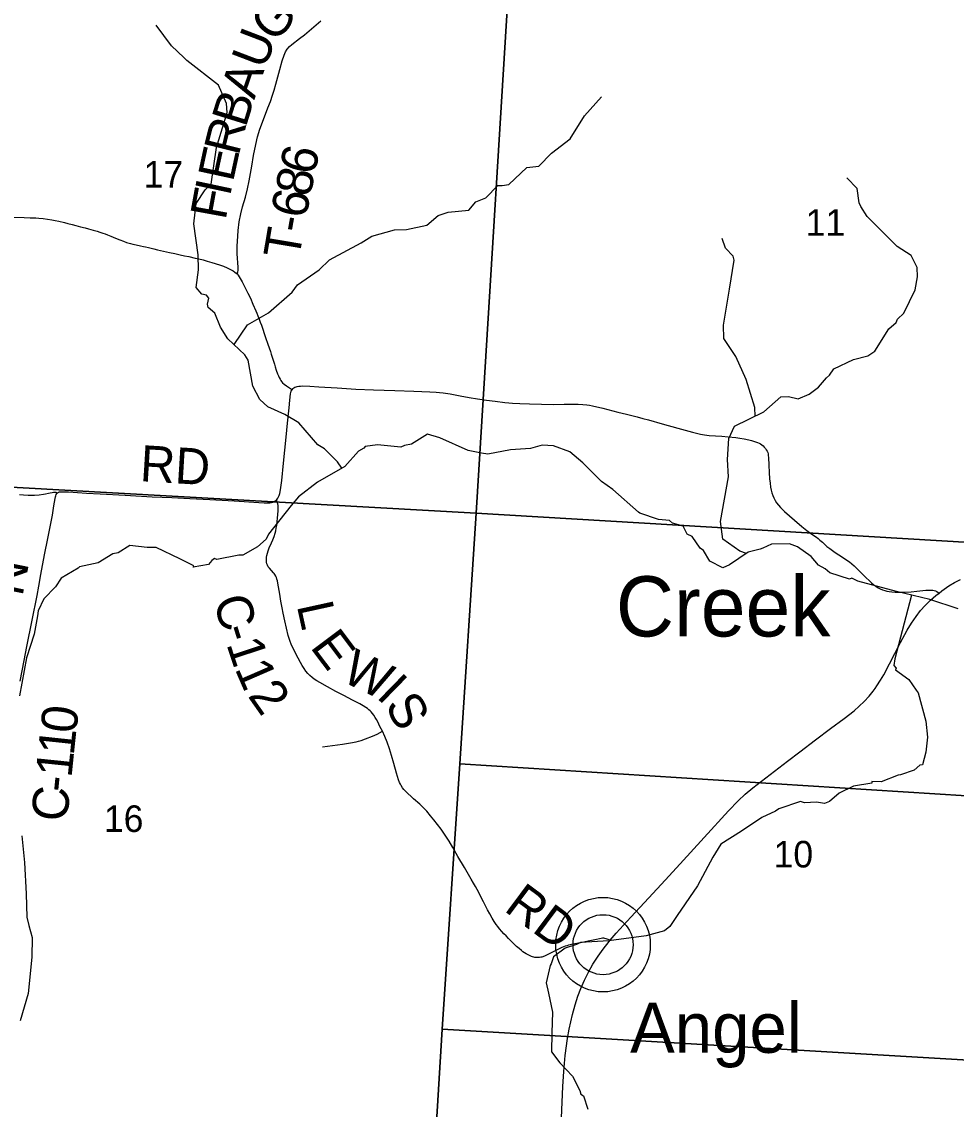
# Model space of a CAD drawing. Extents: x 396.2 to 468.4, y 232.6 to 279.1.
# Drawn here: x 418.928 to 420.398, y 273.414 to 275.126 of the extents above; entities that cross this region are included whole.
import ezdxf

# ---------------------------------------------------------------- set-up
doc = ezdxf.new("R2010")
doc.units = 0
for name, color, linetype in [('GM_X_County_Road', 7, 'Continuous'), ('GM_X_County_Road_Text', 7, 'Continuous'), ('GM_X_Minor_River', 7, 'Continuous'), ('GM_X_Minor_River_Text', 7, 'Continuous'), ('GM_X_Section', 7, 'Continuous'), ('GM_X_Section_Text', 7, 'Continuous'), ('GM_X_State_Route', 7, 'Continuous'), ('GM_X_Township_Road', 7, 'Continuous'), ('GM_X_Township_Road_Text', 7, 'Continuous'), ('GM_X_Unincorporated', 7, 'Continuous'), ('GM_X_Unincorporated_Location', 7, 'Continuous'), ('GM_X_Unincorporated_Text', 7, 'Continuous')]:
    doc.layers.add(name, color=color, linetype=linetype)

msp = doc.modelspace()

# ---------------------------------------------------------------- linework, layer by layer
at = {"layer": 'GM_X_County_Road'}
for points in [[(418.9108, 274.8182), (418.9315, 274.8177), (418.9414, 274.8174), (418.9501, 274.817), (418.9548, 274.8167), (418.9618, 274.8162), (418.9686, 274.8152), (418.9752, 274.8142), (418.9804, 274.8132), (418.9861, 274.8121), (418.9953, 274.8099), (419.0006, 274.8086), (419.0074, 274.8068), (419.0131, 274.8052), (419.0205, 274.8032), (419.0275, 274.8013), (419.033, 274.7998), (419.0404, 274.7977), (419.0464, 274.7961), (419.0506, 274.7949), (419.0553, 274.7933), (419.0593, 274.7919), (419.0628, 274.7905), (419.068, 274.7884), (419.0754, 274.7852), (419.0822, 274.7824), (419.0879, 274.7803), (419.0927, 274.7786), (419.0989, 274.7769), (419.1029, 274.7758), (419.108, 274.7747), (419.1147, 274.7732), (419.1197, 274.7721), (419.1227, 274.7714), (419.1274, 274.7704), (419.1315, 274.7694), (419.1358, 274.7685), (419.1417, 274.7671), (419.1603, 274.7628), (419.1688, 274.761), (419.1772, 274.7591), (419.1841, 274.7576), (419.1906, 274.7562), (419.2006, 274.7539), (419.2067, 274.7525), (419.2133, 274.7509), (419.2198, 274.7491), (419.2269, 274.7472), (419.2392, 274.7432), (419.2453, 274.741), (419.2509, 274.7388), (419.2543, 274.7372), (419.2575, 274.7356), (419.2606, 274.7338), (419.2631, 274.732), (419.2654, 274.7302), (419.2667, 274.7289), (419.2685, 274.7268), (419.2702, 274.7245), (419.2717, 274.722), (419.2747, 274.7166), (419.2802, 274.7059), (419.2837, 274.6987), (419.2877, 274.6906), (419.2917, 274.6812), (419.2963, 274.6708), (419.2978, 274.6671), (419.2994, 274.6631), (419.301, 274.6591), (419.3031, 274.6533), (419.3051, 274.6481), (419.3116, 274.6289), (419.3153, 274.6184), (419.3192, 274.607), (419.3205, 274.6029), (419.3226, 274.5964), (419.3254, 274.5869), (419.3267, 274.5828), (419.3284, 274.5777), (419.3305, 274.5716), (419.3317, 274.5686), (419.3328, 274.566), (419.3343, 274.5633), (419.3355, 274.5613), (419.3368, 274.5596), (419.3382, 274.5578), (419.3407, 274.5556), (419.3443, 274.5529), (419.3521, 274.5476), (419.3533, 274.5467)], [(418.9841, 274.3842), (418.9857, 274.3853), (418.9873, 274.3858), (418.9892, 274.3861), (418.9915, 274.3862), (419.0017, 274.3858), (419.03, 274.3841), (419.0511, 274.3828), (419.0908, 274.3807), (419.133, 274.3783), (419.164, 274.3769), (419.1925, 274.3755), (419.2236, 274.3739), (419.262, 274.3716), (419.3011, 274.3693), (419.3091, 274.3688), (419.3159, 274.3686), (419.3184, 274.3688), (419.3207, 274.3691), (419.3229, 274.3697), (419.3249, 274.3707), (419.3266, 274.3717), (419.3285, 274.3731), (419.3297, 274.3743), (419.3308, 274.3758), (419.3321, 274.378), (419.3331, 274.3804), (419.334, 274.3835), (419.335, 274.3891), (419.3369, 274.4038), (419.3397, 274.4311), (419.3439, 274.4718), (419.3462, 274.4942), (419.3487, 274.5183), (419.3497, 274.5305), (419.3509, 274.5401), (419.3514, 274.5423), (419.3519, 274.5442), (419.3527, 274.5458), (419.3533, 274.5467)], [(419.3533, 274.5467), (419.3548, 274.5486), (419.3562, 274.5497), (419.3578, 274.5507), (419.3596, 274.5515), (419.3615, 274.552), (419.3637, 274.5523), (419.3664, 274.5525), (419.37, 274.5526), (419.3813, 274.5522), (419.3951, 274.5513), (419.4241, 274.5496), (419.4534, 274.5478), (419.4815, 274.5466), (419.5148, 274.5453), (419.5446, 274.5443), (419.5701, 274.5434), (419.5799, 274.5428), (419.5854, 274.5424), (419.5909, 274.5419), (419.602, 274.5402), (419.6179, 274.5373), (419.6319, 274.5345), (419.6448, 274.5322), (419.6591, 274.5303), (419.6728, 274.5286), (419.6878, 274.5268), (419.6943, 274.5263), (419.7003, 274.5258), (419.7115, 274.5252), (419.727, 274.5246), (419.7457, 274.524), (419.7643, 274.5237), (419.7811, 274.524), (419.7932, 274.5241), (419.8035, 274.5239), (419.8107, 274.5236), (419.817, 274.5231), (419.8211, 274.5225), (419.826, 274.5216), (419.8424, 274.5176), (419.8658, 274.5114), (419.8795, 274.508), (419.8961, 274.5039), (419.9051, 274.5016), (419.914, 274.4992), (419.9354, 274.4932), (419.9604, 274.4862), (419.9834, 274.4798), (419.9893, 274.4782), (419.996, 274.4767), (420.0022, 274.4757), (420.0096, 274.4749), (420.0294, 274.4736), (420.0393, 274.4726), (420.0515, 274.4713), (420.0577, 274.4705), (420.0648, 274.4693), (420.0717, 274.468), (420.0761, 274.4669), (420.0794, 274.4659), (420.0824, 274.4649), (420.0854, 274.4637), (420.0879, 274.4626), (420.0902, 274.4614), (420.0923, 274.46), (420.0943, 274.4584), (420.0962, 274.4565), (420.0979, 274.4544), (420.0993, 274.4522), (420.1007, 274.45), (420.1016, 274.4478), (420.1021, 274.4457), (420.1024, 274.4434), (420.1026, 274.4402), (420.1031, 274.4282), (420.1038, 274.4167), (420.1045, 274.4064), (420.1053, 274.3995), (420.1062, 274.3934), (420.107, 274.3885), (420.108, 274.3843), (420.1095, 274.3801), (420.111, 274.3764), (420.1133, 274.3723), (420.1156, 274.3686), (420.1185, 274.3649), (420.1216, 274.3615), (420.1279, 274.3551), (420.1439, 274.3413), (420.1552, 274.3316), (420.1632, 274.3251), (420.1708, 274.3195), (420.1783, 274.3145), (420.1811, 274.3125), (420.1838, 274.31), (420.1876, 274.3068), (420.1913, 274.3033), (420.1948, 274.3), (420.1992, 274.2966), (420.2078, 274.2906), (420.2193, 274.2831), (420.2244, 274.2796), (420.2301, 274.2757), (420.2338, 274.2729), (420.2377, 274.2696), (420.242, 274.2656), (420.2527, 274.2545), (420.2648, 274.2427), (420.2684, 274.2397), (420.2717, 274.2373), (420.2752, 274.2351), (420.2786, 274.2335), (420.2822, 274.232), (420.2856, 274.2308), (420.289, 274.2299), (420.2926, 274.2291), (420.2967, 274.2287), (420.3022, 274.2283), (420.308, 274.2282), (420.3176, 274.2283), (420.3271, 274.2287), (420.3361, 274.2296), (420.3457, 274.2306), (420.3506, 274.231), (420.3556, 274.2312), (420.3591, 274.2312), (420.3612, 274.2311), (420.3634, 274.2308), (420.3657, 274.23), (420.3675, 274.229), (420.3713, 274.2268)], [(418.9255, 274.0883), (418.9315, 274.1206), (418.9359, 274.1425), (418.9441, 274.184), (418.952, 274.2229), (418.9549, 274.2376), (418.9581, 274.2559), (418.9607, 274.27), (418.9643, 274.2895), (418.9684, 274.3102), (418.9726, 274.3309), (418.9761, 274.3493), (418.9785, 274.364), (418.9804, 274.3757), (418.9809, 274.3779), (418.9815, 274.3799), (418.9823, 274.3819), (418.9831, 274.3832), (418.9841, 274.3842)], [(419.8536, 273.6802), (419.8492, 273.6818), (419.8472, 273.6825), (419.8455, 273.683), (419.8435, 273.6834), (419.8416, 273.6833), (419.8396, 273.6831), (419.8297, 273.6811), (419.8189, 273.6788), (419.8097, 273.6769), (419.7954, 273.6741), (419.7884, 273.6724), (419.7856, 273.6717), (419.7829, 273.6708), (419.7778, 273.6688), (419.7725, 273.6665), (419.7631, 273.6616), (419.7587, 273.6593), (419.7537, 273.6569), (419.7504, 273.6554), (419.7464, 273.6539), (419.7444, 273.6534), (419.7424, 273.653), (419.7405, 273.6529), (419.7387, 273.6529), (419.737, 273.6529), (419.7352, 273.6532), (419.7337, 273.6535), (419.7317, 273.654), (419.7299, 273.6547), (419.7278, 273.6555), (419.7245, 273.6572), (419.7215, 273.6588), (419.7189, 273.6605), (419.7165, 273.6622), (419.7141, 273.6642), (419.7103, 273.6673), (419.7066, 273.6705), (419.699, 273.6778), (419.6938, 273.6831), (419.6899, 273.687), (419.6866, 273.6904), (419.6835, 273.6939), (419.6796, 273.6985), (419.677, 273.7017), (419.6743, 273.7053), (419.6714, 273.7098), (419.6681, 273.7152), (419.6643, 273.7218), (419.6608, 273.7284), (419.6576, 273.7346), (419.6543, 273.7408), (419.6509, 273.7476), (419.648, 273.7534), (419.6445, 273.76), (419.6417, 273.7649), (419.6386, 273.7703), (419.635, 273.7764), (419.6243, 273.7946), (419.6142, 273.8121), (419.6063, 273.8261), (419.6002, 273.8363), (419.5942, 273.8457), (419.5877, 273.8549), (419.582, 273.8626), (419.5763, 273.8698), (419.571, 273.8763), (419.5651, 273.8832), (419.5622, 273.8865), (419.5594, 273.8894), (419.5569, 273.8918), (419.5544, 273.8943), (419.5444, 273.9031), (419.5319, 273.9147), (419.5293, 273.9176), (419.5271, 273.9204), (419.525, 273.9236), (419.5237, 273.9259), (419.5224, 273.9286), (419.5208, 273.9326), (419.5173, 273.943), (419.5131, 273.9587), (419.5099, 273.971), (419.5066, 273.9815), (419.503, 273.9918), (419.4993, 274.0011), (419.4954, 274.0091), (419.4915, 274.0168), (419.488, 274.0239), (419.486, 274.0277), (419.4842, 274.031), (419.482, 274.0345), (419.4799, 274.0372), (419.4778, 274.0396), (419.4759, 274.0414), (419.474, 274.0431), (419.4719, 274.0449), (419.4694, 274.0467), (419.4652, 274.0492), (419.4598, 274.0522), (419.4482, 274.0582), (419.4346, 274.0653), (419.4219, 274.0717), (419.4088, 274.079), (419.3968, 274.0857), (419.3921, 274.0887), (419.3881, 274.0914), (419.3847, 274.0939), (419.3814, 274.0967), (419.378, 274.1001), (419.3749, 274.104), (419.3721, 274.1079), (419.3691, 274.1125), (419.3666, 274.1173), (419.3629, 274.124), (419.3599, 274.1299), (419.3568, 274.1359), (419.354, 274.1416), (419.3519, 274.1463), (419.3502, 274.1507), (419.3488, 274.1551), (419.3473, 274.16), (419.3443, 274.1717), (419.3418, 274.183), (419.3391, 274.1951), (419.3374, 274.2036), (419.3357, 274.2139), (419.3339, 274.2251), (419.331, 274.2423), (419.3301, 274.2461), (419.3293, 274.2488), (419.3285, 274.2512), (419.3277, 274.2531), (419.3263, 274.2558), (419.3253, 274.2573), (419.3241, 274.2588), (419.3175, 274.266), (419.3158, 274.2681), (419.3146, 274.2704), (419.3135, 274.2728), (419.313, 274.2755), (419.3128, 274.2776), (419.3129, 274.2801), (419.3132, 274.283), (419.3137, 274.2859), (419.3145, 274.2894), (419.3158, 274.2934), (419.3173, 274.2977), (419.3209, 274.306), (419.323, 274.3107), (419.3249, 274.3157), (419.3266, 274.3211), (419.3275, 274.3247), (419.3284, 274.3291), (419.3292, 274.3333), (419.3299, 274.3393), (419.3305, 274.3448), (419.3314, 274.3562), (419.3314, 274.3594), (419.3314, 274.3618), (419.3312, 274.3644), (419.3306, 274.3671), (419.3298, 274.3695), (419.3285, 274.3731)]]:
    msp.add_lwpolyline(points, dxfattribs=at)
at = {"layer": 'GM_X_Minor_River'}
for points in [[(419.4314, 274.4232), (419.4245, 274.4332), (419.404, 274.4536), (419.3936, 274.46), (419.364, 274.4944), (419.3421, 274.5076), (419.3149, 274.5198), (419.3024, 274.5313), (419.2917, 274.5525), (419.2842, 274.5934), (419.2788, 274.6019), (419.2524, 274.627), (419.2404, 274.6453), (419.2317, 274.6672), (419.2213, 274.6759), (419.2204, 274.6812), (419.2225, 274.691), (419.2185, 274.6957), (419.211, 274.6971), (419.2026, 274.7076), (419.2061, 274.7356), (419.2053, 274.7588), (419.1985, 274.808), (419.2021, 274.8398), (419.2167, 274.8613), (419.2261, 274.8705), (419.2343, 274.928), (419.2511, 274.9833), (419.2503, 274.9973), (419.2376, 275.0259), (419.1874, 275.065), (419.183, 275.0697), (419.1635, 275.0882), (419.1392, 275.1205)], [(419.2619, 274.6179), (419.2833, 274.6488), (419.3163, 274.6675), (419.3536, 274.7005), (419.3619, 274.7116), (419.3959, 274.7352), (419.4122, 274.751), (419.4622, 274.7779), (419.4788, 274.7884), (419.5142, 274.7983), (419.5335, 274.7988), (419.5651, 274.8058), (419.5833, 274.8211), (419.599, 274.8263), (419.6316, 274.8291), (419.6426, 274.8424), (419.6582, 274.8487), (419.677, 274.8679), (419.6838, 274.8681), (419.6944, 274.8696), (419.7224, 274.8964), (419.7414, 274.8985), (419.7613, 274.9191), (419.7907, 274.9417), (419.8134, 274.9778), (419.8403, 275.0077)], [(420.0684, 274.289), (420.0579, 274.2926), (420.0309, 274.3117), (420.0272, 274.3391), (420.0399, 274.4097), (420.0385, 274.4367), (420.0403, 274.4701), (420.0495, 274.4892), (420.0956, 274.512), (420.1224, 274.5354), (420.1345, 274.5362), (420.1495, 274.5323), (420.1667, 274.5397), (420.1814, 274.5506), (420.1943, 274.5654), (420.1986, 274.5698), (420.2057, 274.5795), (420.2368, 274.5941), (420.2589, 274.6002), (420.2701, 274.6074), (420.2919, 274.6428), (420.3039, 274.6523), (420.3056, 274.6576), (420.3157, 274.6671), (420.3335, 274.7041), (420.3375, 274.7245), (420.3368, 274.739), (420.3272, 274.7579), (420.3053, 274.7723), (420.258, 274.8193), (420.2479, 274.8352), (420.2454, 274.841), (420.2423, 274.8635), (420.2262, 274.88)], [(420.082, 274.5053), (420.0814, 274.5189), (420.0676, 274.563), (420.0514, 274.5992), (420.0326, 274.6276), (420.032, 274.6481), (420.0417, 274.7051), (420.0488, 274.7505), (420.0471, 274.757), (420.035, 274.7695), (420.0298, 274.7849)], [(420.4011, 274.202), (420.3568, 274.2164), (420.3043, 274.2292), (420.2434, 274.2454), (420.2339, 274.2503), (420.2305, 274.2488), (420.1995, 274.2586), (420.192, 274.2646), (420.1814, 274.2707), (420.17, 274.2843), (420.1485, 274.2995), (420.136, 274.304), (420.1076, 274.3036), (420.0937, 274.2971), (420.0899, 274.2959), (420.071, 274.2913), (420.0415, 274.2711), (420.0309, 274.2662), (420.0105, 274.2768), (420.0007, 274.2938), (419.9954, 274.2972), (419.9825, 274.3158), (419.9749, 274.3192), (419.9685, 274.3318), (419.9519, 274.3367), (419.9473, 274.3408), (419.9295, 274.3427), (419.9004, 274.3525), (419.8982, 274.354), (419.8581, 274.3897), (419.8403, 274.4022), (419.8108, 274.4317), (419.79, 274.4492), (419.7646, 274.4582), (419.7468, 274.4593), (419.7283, 274.4544), (419.697, 274.452), (419.6611, 274.4455), (419.6512, 274.447), (419.6304, 274.4511), (419.5858, 274.4711), (419.5661, 274.4768), (419.5412, 274.4611), (419.5302, 274.4592), (419.5246, 274.4565), (419.4879, 274.4599), (419.4682, 274.4576), (419.466, 274.4549), (419.458, 274.4499), (419.4362, 274.4257)], [(419.4362, 274.4257), (419.3931, 274.4011), (419.3636, 274.3779), (419.3519, 274.3645), (419.316, 274.3196), (419.3123, 274.3116), (419.299, 274.2994), (419.2756, 274.2861), (419.2696, 274.2864), (419.2348, 274.2795), (419.231, 274.281), (419.2269, 274.278), (419.2219, 274.2719), (419.1978, 274.2676), (419.1985, 274.2695), (419.1766, 274.2805), (419.1395, 274.2983), (419.1251, 274.2986)], [(419.1251, 274.2986), (419.0979, 274.3016), (419.0798, 274.2898), (419.0711, 274.2883), (419.0481, 274.2741), (419.0186, 274.268), (419.0167, 274.2661), (418.9899, 274.25), (418.9808, 274.2367), (418.9627, 274.2177), (418.9536, 274.1987), (418.9529, 274.1907), (418.9472, 274.1618), (418.9352, 274.1245), (418.9246, 274.0648)], [(420.3277, 274.2234), (420.3018, 274.1234)], [(420.3018, 274.1234), (420.3002, 274.1128), (420.3036, 274.1083), (420.3029, 274.106), (420.3237, 274.0908), (420.335, 274.0738), (420.3384, 274.0696), (420.3502, 274.0252), (420.3529, 273.9997), (420.3506, 273.9765), (420.345, 273.9563), (420.3408, 273.956), (420.3321, 273.9479), (420.3106, 273.9407), (420.3068, 273.9399), (420.28, 273.9296), (420.2656, 273.9299), (420.2652, 273.9273), (420.2365, 273.923), (420.2138, 273.9116), (420.1987, 273.8986), (420.1908, 273.8955), (420.1783, 273.8974), (420.1594, 273.8966), (420.1534, 273.8989), (420.119, 273.887), (420.1141, 273.8836), (420.0922, 273.8737), (420.0604, 273.8519), (420.0279, 273.8313), (420.0151, 273.8108), (419.9913, 273.7659), (419.9592, 273.719), (419.9475, 273.7019), (419.9392, 273.695), (419.9105, 273.6874), (419.8515, 273.6792), (419.8069, 273.6765), (419.8005, 273.6738), (419.7831, 273.6677), (419.7646, 273.654), (419.7608, 273.6433), (419.7593, 273.6403), (419.7529, 273.6133), (419.7567, 273.5969), (419.7632, 273.5669), (419.7617, 273.5346), (419.7614, 273.5046), (419.7746, 273.4871), (419.7947, 273.4666), (419.806, 273.4439), (419.8075, 273.4378), (419.8117, 273.4355), (419.8185, 273.4142)], [(418.9279, 273.8447), (418.9321, 273.8025), (418.9351, 273.7531), (418.9359, 273.7166), (418.9393, 273.7037), (418.9443, 273.6844), (418.9439, 273.6539), (418.9379, 273.5965), (418.9255, 273.5535)]]:
    msp.add_lwpolyline(points, dxfattribs=at)
at = {"layer": 'GM_X_Section'}
for points in [[(418.6585, 275.4056), (419.7043, 275.3495), (419.6431, 274.3525), (418.6011, 274.4105)], [(419.7043, 275.3495), (420.7452, 275.2968), (420.6845, 274.2907), (419.6431, 274.3525)], [(418.6011, 274.4105), (419.6431, 274.3525), (419.617, 273.9581), (419.5894, 273.5404), (419.5789, 273.368), (418.9789, 273.3919), (418.5411, 273.4101), (418.5524, 273.5824), (418.5769, 274)], [(419.6431, 274.3525), (420.6845, 274.2907), (420.6634, 273.8917), (419.617, 273.9581)], [(420.6634, 273.8917), (420.6398, 273.4786), (419.5894, 273.5404), (419.617, 273.9581)], [(419.5894, 273.5404), (420.6398, 273.4786), (420.6297, 273.3021), (419.5789, 273.368)]]:
    msp.add_lwpolyline(points, close=True, dxfattribs=at)
at = {"layer": 'GM_X_State_Route'}
for points in [[(419.8536, 273.6802), (419.8631, 273.6912), (419.8861, 273.7166), (419.9146, 273.7472), (419.9401, 273.7746), (419.9639, 273.8008), (420.0016, 273.8421), (420.0398, 273.8838), (420.0553, 273.8999), (420.0661, 273.91), (420.078, 273.9199), (420.1326, 273.9621), (420.1519, 273.9766), (420.1767, 273.9955), (420.2005, 274.0134), (420.2219, 274.0294), (420.2375, 274.0414), (420.2457, 274.0485), (420.2536, 274.0562), (420.2614, 274.0645), (420.2676, 274.0722), (420.2706, 274.0765), (420.2734, 274.0807), (420.279, 274.0894), (420.2841, 274.0981), (420.3107, 274.1491), (420.3212, 274.1682), (420.3277, 274.1792), (420.335, 274.1899), (420.3421, 274.1991), (420.3492, 274.2071), (420.3576, 274.2154), (420.3663, 274.2228), (420.3713, 274.2268), (420.3754, 274.23), (420.3867, 274.2379), (420.3957, 274.2433), (420.4051, 274.248)], [(419.7756, 273.3634), (419.7793, 273.4503), (419.7807, 273.4739), (419.7828, 273.4989), (419.7867, 273.5259), (419.7894, 273.5405), (419.7944, 273.5634), (419.7985, 273.5788), (419.8029, 273.5924), (419.8075, 273.6042), (419.8133, 273.6173), (419.8197, 273.63), (419.8267, 273.6425), (419.8347, 273.655), (419.8425, 273.6662), (419.852, 273.6784), (419.8536, 273.6802)]]:
    msp.add_lwpolyline(points, dxfattribs=at)
at = {"layer": 'GM_X_Township_Road'}
for points in [[(419.2667, 274.7289), (419.2678, 274.7323), (419.2683, 274.7345), (419.2685, 274.7367), (419.2684, 274.7395), (419.2669, 274.7608), (419.2666, 274.7668), (419.2667, 274.7728), (419.2677, 274.7882), (419.2685, 274.7974), (419.2702, 274.8109), (419.2726, 274.8237), (419.2751, 274.8345), (419.2797, 274.85), (419.283, 274.8627), (419.2856, 274.8755), (419.2898, 274.8987), (419.2927, 274.9153), (419.2962, 274.9329), (419.2991, 274.9449), (419.3026, 274.9568), (419.3065, 274.9679), (419.3153, 274.9903), (419.3191, 275.0001), (419.3225, 275.0101), (419.3251, 275.0184), (419.3277, 275.0274), (419.331, 275.0394), (419.3342, 275.0507), (419.3378, 275.0645), (419.3407, 275.0734), (419.3429, 275.0784), (419.3455, 275.0825), (419.349, 275.0868), (419.3526, 275.0901), (419.3651, 275.0993), (419.3729, 275.1054), (419.3877, 275.1178), (419.3983, 275.1274)], [(418.9245, 274.382), (418.9305, 274.3814), (418.9379, 274.3809), (418.9478, 274.3808), (418.9552, 274.3814), (418.9619, 274.3824), (418.9655, 274.3831), (418.9698, 274.384), (418.9728, 274.3847), (418.9758, 274.3852), (418.9778, 274.3855), (418.9793, 274.3856), (418.9803, 274.3855), (418.9814, 274.3853), (418.9827, 274.3848), (418.9841, 274.3842)], [(419.401, 273.9845), (419.4166, 273.9868), (419.4324, 273.989), (419.4453, 273.9909), (419.4539, 273.9927), (419.4578, 273.9936), (419.4617, 273.9947), (419.4688, 273.9971), (419.4798, 274.0015), (419.4872, 274.0048), (419.4954, 274.0091)]]:
    msp.add_lwpolyline(points, dxfattribs=at)
at = {"layer": 'GM_X_Unincorporated'}
for radius in [0.0744, 0.0472]:
    msp.add_circle((419.8425, 273.6733), radius, dxfattribs=at)
at = {"layer": 'GM_X_Unincorporated_Location'}
msp.add_line((419.8425, 273.6733), (419.8425, 273.6733), dxfattribs=at)

# ---------------------------------------------------------------- texts
at = {"layer": 'GM_X_County_Road_Text'}
for s, height, rotation, p in [('RD', 0.05682, 356.5467, (419.113, 274.4029)), ('N', 0.0568, 78.5982, (418.9288, 274.2202)), ('C', 0.0568, 286.8772, (419.2287, 274.215)), ('L', 0.0568, 282.361, (419.3605, 274.2072)), ('-', 0.0568, 287.1602, (419.2423, 274.1701)), ('E', 0.0568, 306.9638, (419.3806, 274.1417)), ('1', 0.0568, 288.1955, (419.2496, 274.1467)), ('W', 0.0568, 334.3897, (419.4289, 274.0891)), ('1', 0.0568, 293.4754, (419.2625, 274.1081)), ('I', 0.0568, 315.7314, (419.4843, 274.0634)), ('2', 0.0568, 305.1273, (419.2826, 274.065)), ('S', 0.0568, 298.4736, (419.4983, 274.0507)), ('0', 0.0568, 83.261, (419.0133, 274.0044)), ('1', 0.0568, 83.9313, (419.0096, 273.9698)), ('1', 0.0568, 84.1509, (419.0061, 273.935)), ('C', 0.0568, 84.2255, (418.999, 273.8654)), ('-', 0.0568, 84.2059, (419.0037, 273.9118)), ('RD', 0.05682, 323.3346, (419.685, 273.7277))]:
    msp.add_text(s, height=height, rotation=rotation, dxfattribs=at).set_placement(p)
at = {"layer": 'GM_X_Minor_River_Text'}
msp.add_text('Creek', height=0.0947, rotation=359.997, dxfattribs=at).set_placement((419.8627, 274.1584))
at = {"layer": 'GM_X_Section_Text'}
for s, p in [('17', (419.1196, 274.8649)), ('11', (420.1613, 274.789)), ('16', (419.0571, 273.8507)), ('10', (420.1108, 273.7948))]:
    msp.add_text(s, height=0.04186, rotation=0, dxfattribs=at).set_placement(p)
at = {"layer": 'GM_X_Township_Road_Text'}
for s, rotation, p in [('G', 47.346, (419.3245, 275.0909)), ('U', 69.0963, (419.3097, 275.049)), ('A', 71.307, (419.2938, 275.0022)), ('B', 72.6895, (419.2801, 274.958)), ('R', 76.1223, (419.2691, 274.9135)), ('E', 77.7836, (419.2602, 274.8724)), ('6', 78.0221, (419.3885, 274.883)), ('8', 78.5482, (419.3816, 274.8488)), ('F', 79.6956, (419.2486, 274.8124)), ('I', 77.9606, (419.2554, 274.8496)), ('6', 79.2004, (419.375, 274.8146)), ('-', 79.9493, (419.371, 274.7918)), ('T', 80.3939, (419.3639, 274.7501))]:
    msp.add_text(s, height=0.0568, rotation=rotation, dxfattribs=at).set_placement(p)
at = {"layer": 'GM_X_Unincorporated_Text'}
msp.add_text('Angel', height=0.07898, rotation=0, dxfattribs=at).set_placement((419.885, 273.5031))

doc.saveas('drawing.dxf')
